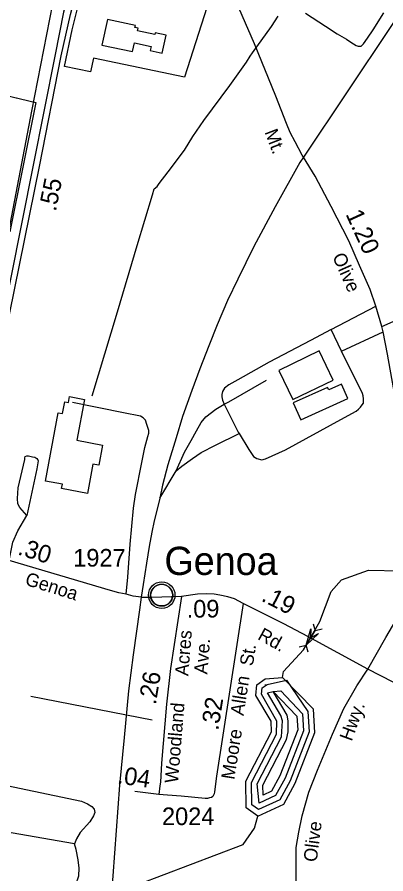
# Model space of a CAD drawing. Extents: x 2206922 to 2357709, y 510027 to 673830.
# Drawn here: x 2288072 to 2290689, y 573456 to 579534 of the extents above; entities that cross this region are included whole.
import ezdxf

# ---------------------------------------------------------------- set-up
doc = ezdxf.new("R2010")
doc.units = 0
for name, color, linetype in [('Exist Boundary Political City Limit New', 7, 'Continuous'), ('Exist Boundary Political Urban Extension UEB', 7, 'Continuous'), ('Exist Civil Demographics Community CELL', 7, 'Continuous'), ('Exist Civil Demographics Community Label', 7, 'Continuous'), ('Exist Cultural Manufacturing Building Footprint', 7, 'Continuous'), ('Exist Cultural Warehouse Building Footprint', 7, 'Continuous'), ('Exist Hydrographic Buffer Line', 7, 'Continuous'), ('Exist Hydrographic Creek Single Shore', 7, 'Continuous'), ('Exist Hydrographic Lake Shore', 7, 'Continuous'), ('Exist Hydrographic Misc Water Feature', 7, 'Continuous'), ('Exist Railroad Mainline', 7, 'Continuous'), ('Exist Railroad Siding', 7, 'Continuous'), ('Exist Road Non-System Type 51', 7, 'Continuous'), ('Exist Road Primary US Divided Attributed', 7, 'Continuous'), ('Exist Road Primary US Mileage Tenths English Label', 7, 'Continuous'), ('Exist Road Secondary Mileage Hundredths English Label', 7, 'Continuous'), ('Exist Road Secondary Structure Pipe Attributed CELL', 7, 'Continuous'), ('Exist Road Secondary Structure Pipe CELL', 7, 'Continuous'), ('Exist Road Secondary Type 51 Attributed', 7, 'Continuous'), ('Exist Road Secondary Type 51 Label', 7, 'Continuous'), ('Exist Road Secondary Type 51 Number Label', 7, 'Continuous'), ('Map Preparation Boundary City Limit Buffer Line', 7, 'Continuous')]:
    doc.layers.add(name, color=color, linetype=linetype)

msp = doc.modelspace()

# ---------------------------------------------------------------- linework, layer by layer
at = {"layer": 'Exist Boundary Political City Limit New'}
for points in [[(2289497.5, 579856.1), (2289259.8, 579109.1), (2288613.8, 579243.1), (2288593.5, 579145.1), (2288408.8, 579183.4), (2288461.8, 579444.8), (2288507, 579624.6)], [(2287926.2, 578994.3), (2288204.5, 578927.9), (2288019.5, 578010)]]:
    msp.add_lwpolyline(points, dxfattribs=at)
at = {"layer": 'Exist Boundary Political Urban Extension UEB'}
msp.add_line((2287895.1, 577405.1), (2288177.3, 578865.9), dxfattribs=at)
msp.add_lwpolyline([(2288177.3, 578865.9), (2288366.9, 579847.5), (2288582.3, 580340.1), (2288624.6, 580399.1)], dxfattribs=at)
at = {"layer": 'Exist Civil Demographics Community CELL'}
msp.add_lwpolyline([(2289020.1, 575445.7), (2289021, 575451.3), (2289022.8, 575457.8), (2289025.7, 575465), (2289028.7, 575470.8), (2289032, 575476.5), (2289035.8, 575481.6), (2289039.7, 575486), (2289044.3, 575490.6), (2289049.8, 575495.2), (2289055.3, 575498.8), (2289060.2, 575501.7), (2289065.2, 575504.2), (2289070.7, 575506.5), (2289076.3, 575508.3), (2289080.6, 575509.4), (2289085.5, 575510.2), (2289089.6, 575510.9), (2289096, 575511.2), (2289100.4, 575511.1), (2289106.1, 575510.8), (2289111, 575510.1), (2289115.9, 575509.1), (2289120.9, 575507.7), (2289126.1, 575505.7), (2289132.7, 575502.8), (2289139, 575499.3), (2289144, 575495.8), (2289149.2, 575491.7), (2289152.5, 575488.6), (2289156.6, 575484.2), (2289160.5, 575479.5), (2289163.6, 575474.9), (2289166.7, 575469.9), (2289169.2, 575464.8), (2289171.2, 575459.8), (2289172.8, 575454.8), (2289174, 575450.2), (2289175.1, 575444.1), (2289175.8, 575439.4), (2289176, 575433.4), (2289175.8, 575427.6), (2289175.3, 575421.9), (2289174.3, 575416.5), (2289172.7, 575410.3), (2289170.8, 575404.5), (2289168.5, 575399.4), (2289165.3, 575393.4), (2289162.1, 575388.1), (2289158.6, 575383.4), (2289154.4, 575378.6), (2289149.1, 575373.7), (2289144.1, 575369.5), (2289139.1, 575366.1), (2289134.7, 575363.6), (2289127.9, 575360.4), (2289120.8, 575357.6), (2289114.8, 575356.2), (2289108.2, 575354.9), (2289103.8, 575354.4), (2289099.3, 575354.2), (2289093.7, 575354.2), (2289089.5, 575354.6), (2289083.8, 575355.3), (2289077.9, 575356.6), (2289073.3, 575357.9), (2289068.1, 575359.8), (2289063.5, 575361.8), (2289059.6, 575364), (2289052.8, 575368.1), (2289047.2, 575372.4), (2289042.3, 575376.8), (2289037.9, 575381.7), (2289034.7, 575385.7), (2289031.7, 575389.8), (2289027.6, 575396.9), (2289025.9, 575400.5), (2289024.2, 575404.5), (2289021.6, 575412.7), (2289020.1, 575419.7), (2289019.4, 575424.9), (2289019, 575431.2), (2289019, 575435.9), (2289019.5, 575442.4)], close=True, dxfattribs=at)
for centre, radius in [((2289097.7, 575433.3), 94.3), ((2289097.4, 575433.5), 76.7)]:
    msp.add_circle(centre, radius, dxfattribs=at)
at = {"layer": 'Exist Cultural Manufacturing Building Footprint'}
for p, q in [((2288713.3, 579516.7), (2288674, 579336.1)), ((2288911, 579473.7), (2288713.3, 579516.7)), ((2288908.1, 579460.3), (2288911, 579473.7)), ((2288930, 579455.5), (2288908.1, 579460.3)), ((2288926.1, 579437.7), (2288930, 579455.5)), ((2289049, 579411), (2288926.1, 579437.7)), ((2289051.7, 579423.2), (2289049, 579411)), ((2289129.5, 579406.3), (2289051.7, 579423.2)), ((2289101.6, 579278), (2289129.5, 579406.3)), ((2288674, 579336.1), (2288890.3, 579289.1)), ((2288890.3, 579289.1), (2288903.9, 579351.8)), ((2288903.9, 579351.8), (2289022.4, 579326.1)), ((2289022.4, 579326.1), (2289016, 579296.6)), ((2289016, 579296.6), (2289101.6, 579278))]:
    msp.add_line(p, q, dxfattribs=at)
at = {"layer": 'Exist Cultural Warehouse Building Footprint'}
for p, q in [((2290216.1, 577166.1), (2289927.9, 577027.6)), ((2290315.4, 576959.4), (2290216.1, 577166.1)), ((2289927.9, 577027.6), (2290027.2, 576820.9)), ((2290027.2, 576820.9), (2290315.4, 576959.4)), ((2290372.6, 576930.1), (2290282.9, 576889.5)), ((2290418.7, 576828.2), (2290372.6, 576930.1)), ((2290274.8, 576907.3), (2290030.9, 576796.8)), ((2290282.9, 576889.5), (2290274.8, 576907.3)), ((2288393.6, 576720.9), (2288409.3, 576805)), ((2288409.3, 576805), (2288436, 576800)), ((2288436, 576800), (2288443.9, 576842.2)), ((2288443.9, 576842.2), (2288550.2, 576822.3)), ((2288550.2, 576822.3), (2288496, 576532)), ((2290085, 576677.1), (2290418.7, 576828.2)), ((2290030.9, 576796.8), (2290085, 576677.1)), ((2288273.7, 576242.9), (2288364, 576726.5)), ((2288364, 576726.5), (2288393.6, 576720.9)), ((2288496, 576532), (2288678.7, 576497.9)), ((2288678.7, 576497.9), (2288652.1, 576355.4)), ((2288609.4, 576363.4), (2288570.4, 576154.7)), ((2288652.1, 576355.4), (2288609.4, 576363.4)), ((2288393.3, 576220.6), (2288273.7, 576242.9)), ((2288387.4, 576188.9), (2288393.3, 576220.6)), ((2288570.4, 576154.7), (2288387.4, 576188.9))]:
    msp.add_line(p, q, dxfattribs=at)
at = {"layer": 'Exist Hydrographic Buffer Line'}
for points in [[(2289982.7, 574829.4), (2290134.9, 574608.3), (2290143.5, 574464.4), (2290009.6, 574117.1), (2289935.1, 573981.7), (2289784.8, 573912.1), (2289737.7, 573944.7), (2289735.8, 574104.3), (2289911.3, 574446.1), (2289914.8, 574540.4), (2289806.2, 574731.5), (2289810.9, 574775.6), (2289845.1, 574800.2), (2289982.7, 574829.4)], [(2289788.9, 573958), (2289776.2, 574094.9), (2289947.2, 574427.8), (2289954.8, 574540.9), (2289944.2, 574579.8), (2289847.4, 574740.6), (2289888.6, 574750.1), (2289944, 574753.5), (2290095.9, 574591), (2290102.9, 574470.7), (2289973.1, 574134), (2289906.4, 574012.5), (2289788.9, 573958)], [(2289816.8, 574015.1), (2289816.2, 574085.4), (2289982.7, 574409.6), (2289995.8, 574464.4), (2289994.8, 574541.4), (2289987.6, 574580.9), (2289888.6, 574750.1), (2290056.9, 574573.7), (2290062.7, 574477), (2289937, 574150.9), (2289877.7, 574043.3), (2289816.8, 574015.1)]]:
    msp.add_lwpolyline(points, dxfattribs=at)
at = {"layer": 'Exist Hydrographic Creek Single Shore'}
for points in [[(2289954.8, 574849.7), (2289962.8, 574892.2), (2290105, 575045.8), (2290154.2, 575129.4), (2290219.4, 575247.2), (2290299.9, 575459.3), (2290373.9, 575543.1), (2290564.8, 575611.3), (2290789.8, 575606.8), (2291214.9, 575535.9), (2291505.8, 575579.2), (2291671.9, 575631.6), (2291763, 575715), (2292154.8, 576586.1), (2292161, 576825.3), (2292032, 577201.7), (2292048, 577342.5), (2292129.8, 577426.1), (2292270.9, 577501.9), (2292645.9, 577487.8)], [(2288292.9, 572758.2), (2288605, 573178.2), (2288703.8, 573271.4), (2288927.9, 573381.6), (2289674.9, 573664.9), (2289756.9, 573781.3), (2289780.9, 573866.1)]]:
    msp.add_lwpolyline(points, dxfattribs=at)
at = {"layer": 'Exist Hydrographic Lake Shore'}
for points in [[(2289780.9, 573866.1), (2289697.9, 573923.6), (2289695.8, 574113.8), (2289875.9, 574464.4), (2289874.8, 574539.8), (2289764.9, 574722.4), (2289772.9, 574797.6), (2289831, 574839.2), (2289954.8, 574849.7)], [(2289780.9, 573866.1), (2289963.8, 573951), (2290045.9, 574100.2), (2290183.9, 574458.1), (2290173.8, 574625.6), (2289954.8, 574849.7)]]:
    msp.add_lwpolyline(points, dxfattribs=at)
at = {"layer": 'Exist Hydrographic Misc Water Feature'}
msp.add_line((2289833.8, 574795.5), (2289834.9, 574799.8), dxfattribs=at)
for points in [[(2288603.3, 576846.6), (2288783.6, 577444), (2288923.4, 577913.3), (2289031.9, 578274), (2289045.2, 578316.2), (2289064.9, 578332.3), (2289078.8, 578354.6), (2289144, 578436.8), (2289258.7, 578589.8), (2289317.7, 578686.4), (2289396.7, 578801), (2289582, 579048.8), (2289700.4, 579213.9), (2289726.2, 579255.9), (2289742, 579281.9), (2289876.1, 579467.2), (2289925.1, 579539.8)], [(2290119.3, 579561.6), (2290259.9, 579470.7), (2290342.2, 579415.7), (2290408.6, 579378.1), (2290440.8, 579356.7), (2290476.9, 579333), (2290490.8, 579327.2), (2290512.8, 579327.1), (2290530.8, 579343.5), (2290558.3, 579385.6), (2290597.7, 579444.1), (2290674.3, 579564.8)]]:
    msp.add_lwpolyline(points, dxfattribs=at)
at = {"layer": 'Exist Railroad Mainline'}
for points in [[(2292775.6, 582519), (2292752.6, 582485), (2291559.4, 580720.4), (2291033.1, 579934), (2290104.4, 578539.8)], [(2290104.4, 578539.8), (2290079.1, 578501.8), (2289902, 578188.3), (2289750.8, 577907.1), (2289637.2, 577674.1), (2289564.5, 577523.4), (2289492.3, 577350.9), (2289431.7, 577202.4), (2289367.2, 577038), (2289310.7, 576885.4), (2289246.4, 576701), (2289200, 576548.6), (2289141.7, 576358.2), (2289103, 576213.9), (2289084, 576121.7)], [(2289084, 576121.7), (2289068.6, 576053.6), (2289043.5, 575959.6), (2289028.3, 575879.3), (2289009.3, 575777.3), (2288990.3, 575661.3), (2288965.8, 575508.9), (2288952.5, 575417.9)], [(2288952.5, 575417.9), (2288939.4, 575328.9), (2288894.6, 575010.5), (2288861, 574754.3), (2288832.1, 574422.3), (2288797.4, 574086.4), (2288738.9, 573282.2), (2288399.4, 568789.4), (2288395.5, 568735.1), (2288273, 567057.4), (2288112.4, 564856.3), (2288039.1, 563851.4), (2288038, 563836.6), (2287853.8, 561437.5), (2287845.7, 561332.3), (2287845.6, 561330.8)]]:
    msp.add_lwpolyline(points, dxfattribs=at)
at = {"layer": 'Exist Railroad Siding'}
msp.add_line((2289084, 576121.7), (2289200, 576314.7), dxfattribs=at)
for points in [[(2289200, 576314.7), (2289258.9, 576447.2), (2289305.9, 576529.6), (2289345.4, 576600), (2289376.7, 576658.2), (2289410.3, 576698.5), (2289481.8, 576753.2), (2289541.9, 576787.9), (2289573.2, 576805.9), (2289841.6, 576958.4)], [(2289200, 576314.7), (2289239.7, 576349), (2289315.2, 576403.7), (2289378.8, 576444.4), (2289480.2, 576497.3), (2289647.2, 576579.1)]]:
    msp.add_lwpolyline(points, dxfattribs=at)
at = {"layer": 'Exist Road Non-System Type 51'}
for p, q in [((2290300.1, 577318.6), (2290616.3, 577483.4)), ((2290373.5, 577163.4), (2290300.1, 577318.6)), ((2290373.5, 577163.4), (2290670, 577301.9)), ((2288479.5, 573669.5), (2288028.8, 573747.2))]:
    msp.add_line(p, q, dxfattribs=at)
for points in [[(2290659.6, 577339.9), (2290805, 577403.2), (2291007.9, 577501), (2291197, 577596.8), (2291361.9, 577694.4), (2291506.9, 577797.6), (2291619.9, 577896.7), (2291716.9, 577987.5), (2291819.8, 578114.4), (2291946, 578293.6), (2292030.7, 578422.2), (2292058.1, 578482.4), (2292071.5, 578532.5)], [(2290300.1, 577318.6), (2290153, 577239.2), (2289860.4, 577086.6), (2289637.7, 576960.6), (2289574.1, 576925.9), (2289542.4, 576901.7), (2289528.7, 576877.6), (2289524.9, 576857.5), (2289524.9, 576839.5), (2289529.3, 576817.6), (2289541.9, 576787.9)], [(2289647.2, 576579.1), (2289716.5, 576465.6), (2289748.9, 576417.9), (2289773, 576402), (2289809, 576392.5), (2289834.9, 576400.6), (2289976.4, 576463.9), (2290368, 576679.5), (2290477.3, 576738.5), (2290495.2, 576752.7), (2290509.1, 576766.8), (2290521, 576783), (2290528.8, 576795), (2290530.7, 576810.9), (2290530.5, 576826.9), (2290528.3, 576847), (2290522.2, 576864.9), (2290373.5, 577163.4)], [(2288844.5, 575439.8), (2288857.4, 575561.9), (2288875.1, 575796), (2288898.8, 576050.1), (2288911.8, 576146.2), (2288957.8, 576374.5), (2288978.7, 576480.7), (2288999.9, 576558.8), (2289005.7, 576582.7), (2289005.5, 576600.7), (2288993.2, 576644.7), (2288982.8, 576674.5), (2288966.7, 576690.4), (2288946.6, 576702.2), (2288826.3, 576727.1), (2288463.9, 576799.6)], [(2289541.9, 576787.9), (2289543.6, 576783.7), (2289641.2, 576588.8), (2289647.2, 576579.1)], [(2288141.7, 575999), (2288091.2, 576054.4), (2288077, 576082.3), (2288074.5, 576118.3), (2288079.9, 576194.4), (2288125.9, 576394.6), (2288125.7, 576406.6), (2288129.7, 576416.7), (2288141.6, 576420.8), (2288151.6, 576420.8), (2288181.7, 576415.2), (2288197.8, 576411.3), (2288211.8, 576403.4), (2288217.8, 576393.5), (2288220.1, 576385.5), (2288210.5, 576329.5), (2288141.7, 575999)], [(2288015.2, 575678.3), (2288040.3, 575809.3), (2288077.9, 575888.8), (2288141.7, 575999)], [(2287999.8, 574082.7), (2288528.5, 573971.8), (2288570.7, 573952.2), (2288600.8, 573934.6), (2288619, 573914.6), (2288623.3, 573890.8), (2288613.4, 573866.8), (2288587.9, 573824.5), (2288518.7, 573749.9), (2288493.1, 573703.7), (2288479.5, 573669.5)], [(2287970.1, 573189), (2288082, 573206), (2288201.5, 573233.1), (2288271.5, 573249.7), (2288333.2, 573276.3), (2288394.9, 573305), (2288456.5, 573345.5), (2288488, 573381.7), (2288509.4, 573441.8), (2288512.9, 573495.9), (2288504.3, 573555.9), (2288489.8, 573629.6), (2288479.5, 573669.5)]]:
    msp.add_lwpolyline(points, dxfattribs=at)
at = {"layer": 'Exist Road Primary US Divided Attributed'}
for points in [[(2288672.5, 580293.8), (2288641.2, 580235.2), (2288604.1, 580161), (2288567, 580068.1), (2288521.5, 579960.1), (2288482.7, 579852.1), (2288440.5, 579722.2), (2288401.7, 579570.3), (2288341.1, 579268.2), (2288186.3, 578484.2), (2287941.4, 577270.2), (2287870.4, 576918.4)], [(2287914.5, 576909.9), (2287985.4, 577261.3), (2288230.3, 578475.4), (2288385.1, 579259), (2288449.7, 579552.7), (2288490.3, 579709.4), (2288530.8, 579833.8), (2288575.4, 579939.9), (2288624.4, 580058), (2288661.5, 580145.8), (2288688.5, 580198.1), (2288718.1, 580251.5)]]:
    msp.add_lwpolyline(points, dxfattribs=at)
at = {"layer": 'Exist Road Secondary Structure Pipe Attributed CELL'}
msp.add_lwpolyline([(2290210.7, 575161.4), (2290122.4, 575077.4), (2290156.9, 575194.3), (2290154.2, 575129.4)], close=True, dxfattribs=at)
at = {"layer": 'Exist Road Secondary Structure Pipe CELL'}
for p, q in [((2290172.4, 575230), (2290185.7, 575181)), ((2290122.7, 575077.7), (2290185.7, 575181)), ((2290235.3, 575191.6), (2290185.7, 575181)), ((2290073.1, 575067.1), (2290122.7, 575077.7)), ((2290136, 575028.7), (2290122.7, 575077.7))]:
    msp.add_line(p, q, dxfattribs=at)
at = {"layer": 'Exist Road Secondary Type 51 Attributed'}
msp.add_line((2289077.9, 574019.5), (2288907.6, 574040.6), dxfattribs=at)
for points in [[(2290104.4, 578539.8), (2290094.6, 578555.9), (2290043.7, 578649.5), (2290009, 578715), (2289984.5, 578778.8), (2289908.7, 578973.9), (2289755.3, 579344.3), (2289493.8, 579949.5), (2289273, 580469.2), (2289138.2, 580748.8), (2289105.8, 580815.9)], [(2290559.5, 574909.1), (2290688.5, 575132.5), (2290790.9, 575306.3), (2290851.6, 575424.8), (2290887.6, 575513.9), (2290910.5, 575599.2), (2290924.5, 575660.3), (2290934.7, 575718.9), (2290937.3, 575806.8), (2290934.7, 575874.2), (2290923.3, 575976.1), (2290813.2, 576507.8), (2290699.4, 577142.4), (2290670, 577301.9), (2290659.6, 577339.9), (2290616.3, 577483.4), (2290577.1, 577602.9), (2290501.6, 577772.2), (2290426, 577947.4), (2290299.9, 578190.1), (2290185.9, 578404.9), (2290104.4, 578539.8)], [(2288952.5, 575417.9), (2288894.6, 575426.4), (2288844.5, 575439.8), (2288794, 575449), (2288734.3, 575466.8), (2288015.2, 575678.3), (2287747.1, 575744.2), (2287681.2, 575760.5)], [(2289238.7, 575423.2), (2289026.7, 575415.5), (2288958.6, 575416.9), (2288952.5, 575417.9)], [(2289238.7, 575423.2), (2289160.2, 574913.8), (2289131.5, 574659.1), (2289097.1, 574241.6), (2289088.5, 574106.6), (2289084.6, 574081.7), (2289077.9, 574019.5)], [(2289676, 575374.4), (2289614.8, 575406.9), (2289566.9, 575422.2), (2289511.4, 575433.7), (2289469.3, 575441.4), (2289413.8, 575443.3), (2289352.6, 575441.4), (2289238.7, 575423.2)], [(2289676, 575374.4), (2289485.5, 574149.2), (2289473.3, 574038.4), (2289469.9, 574024.8), (2289465.8, 574015), (2289459.8, 574005.2), (2289451.8, 573998.8), (2289437.7, 573994.6), (2289423.2, 573991.6), (2289407, 573991.6), (2289234.9, 574006.1), (2289139.2, 574013.8), (2289077.9, 574019.5)], [(2290559.5, 574909.1), (2290134.8, 575138.8), (2289964.3, 575230.5), (2289676, 575374.4)], [(2289826.5, 570767), (2290021.1, 572007.2), (2290052.4, 572204.5), (2290067.7, 572359), (2290072.8, 572452.2), (2290069.6, 572639.2), (2290063.2, 572874.1), (2290055.5, 573170.3), (2290051.7, 573356.7), (2290053, 573529), (2290051.7, 573642.6), (2290070.9, 573751.2), (2290095.1, 573867.3), (2290141, 574035.9), (2290203.6, 574191.6), (2290309.5, 574448.2), (2290391.1, 574628.2), (2290483, 574790.4), (2290559.5, 574909.1)], [(2292381.1, 573526.4), (2292346.8, 573572.6), (2292343.3, 573577.1), (2292280.6, 573659.1), (2292122.8, 573864.2), (2291928.1, 574122.7), (2291846.6, 574218.2), (2291827.5, 574236), (2291798.2, 574256.4), (2291638.5, 574348.7), (2291219.8, 574571.5), (2290924.8, 574722.4), (2290559.5, 574909.1)]]:
    msp.add_lwpolyline(points, dxfattribs=at)
at = {"layer": 'Exist Road Secondary Type 51 Number Label'}
msp.add_line((2289029.9, 574546.5), (2288169.1, 574714.1), dxfattribs=at)
at = {"layer": 'Map Preparation Boundary City Limit Buffer Line'}
for points in [[(2289497.5, 579856.1), (2289259.8, 579109.1), (2288613.8, 579243.1), (2288593.5, 579145.1), (2288408.8, 579183.4), (2288461.8, 579444.8), (2288507, 579624.6)], [(2287926.2, 578994.3), (2288204.5, 578927.9), (2288019.5, 578010)]]:
    msp.add_lwpolyline(points, dxfattribs=at)

# ---------------------------------------------------------------- texts
at = {"layer": 'Exist Civil Demographics Community Label'}
msp.add_text('Genoa', height=200, dxfattribs=at).set_placement((2289116.9, 575576.5))
at = {"layer": 'Exist Road Primary US Mileage Tenths English Label'}
msp.add_text('.55', height=125, rotation=78.7407, dxfattribs=at).set_placement((2288346.2, 578151))
at = {"layer": 'Exist Road Secondary Mileage Hundredths English Label'}
for s, rotation, p in [('1.20', 294.60737, (2290401, 578136.1)), ('.30', 342.59791, (2288069.8, 575723.5)), ('.19', 332.88399, (2289798, 575396)), ('.09', 0.55661, (2289275.6, 575273.2)), ('.26', 80.69047, (2289055.6, 574651.8)), ('.32', 81.0171, (2289498.9, 574469.5)), ('.04', 351.66949, (2288778.4, 574099.2))]:
    msp.add_text(s, height=125, rotation=rotation, dxfattribs=at).set_placement(p)
at = {"layer": 'Exist Road Secondary Type 51 Label'}
for s, rotation, p in [('Mt.', 291.00611, (2289826.2, 578718.9)), ('Olive', 294.03456, (2290306.8, 577836.6)), ('Genoa', 342.59791, (2288121.8, 575508.5)), ('Acres', 85.33391, (2289286.1, 574857.5)), ('Rd.', 331.01717, (2289772.3, 575123.9)), ('Ave.', 85.33391, (2289421.2, 574869.6)), ('St.', 81.0171, (2289744.1, 574926.2)), ('Allen', 81.0171, (2289678, 574574.8)), ('Woodland', 85.33391, (2289213.3, 574096.7)), ('Hwy.', 69.84857, (2290445.4, 574391.8)), ('Moore', 81.0171, (2289612.7, 574120.7)), ('Olive', 82.63833, (2290197.5, 573536.6))]:
    msp.add_text(s, height=95, rotation=rotation, dxfattribs=at).set_placement(p)
at = {"layer": 'Exist Road Secondary Type 51 Number Label'}
for s, p in [('1927', (2288469.9, 575636)), ('2024', (2289099.9, 573801.9))]:
    msp.add_text(s, height=125, dxfattribs=at).set_placement(p)

doc.saveas('drawing.dxf')
